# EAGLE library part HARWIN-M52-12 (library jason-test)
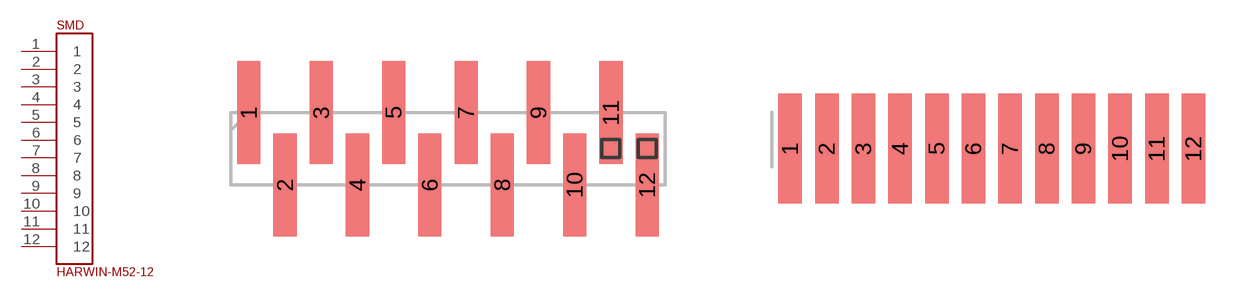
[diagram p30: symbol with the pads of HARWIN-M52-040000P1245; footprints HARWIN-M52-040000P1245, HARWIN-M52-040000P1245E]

Designator prefix SMD

## HARWIN-M52-12SMD  [HARWIN-M52-040000P1245]
1  1
2  2
3  3
4  4
5  5
6  6
7  7
8  8
9  9
10  10
11  11
12  12

## HARWIN-M52-12SMDE  [HARWIN-M52-040000P1245E]
Pads as for HARWIN-M52-040000P1245

## Footprint HARWIN-M52-040000P1245 (pad centres in mm)
smd 0.813 x 3.607: 1 -6.985,1.27; 2 -5.715,-1.27; 3 -4.445,1.27; 4 -3.175,-1.27; 5 -1.905,1.27; 6 -0.635,-1.27; 7 0.635,1.27; 8 1.905,-1.27; 9 3.175,1.27; 10 4.445,-1.27; 11 5.715,1.27; 12 6.985,-1.27

## Footprint HARWIN-M52-040000P1245E (pad centres in mm)
smd 0.813 x 3.81: 1 -6.985,1.905; 2 -5.715,1.905; 3 -4.445,1.905; 4 -3.175,1.905; 5 -1.905,1.905; 6 -0.635,1.905; 7 0.635,1.905; 8 1.905,1.905; 9 3.175,1.905; 10 4.445,1.905; 11 5.715,1.905; 12 6.985,1.905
